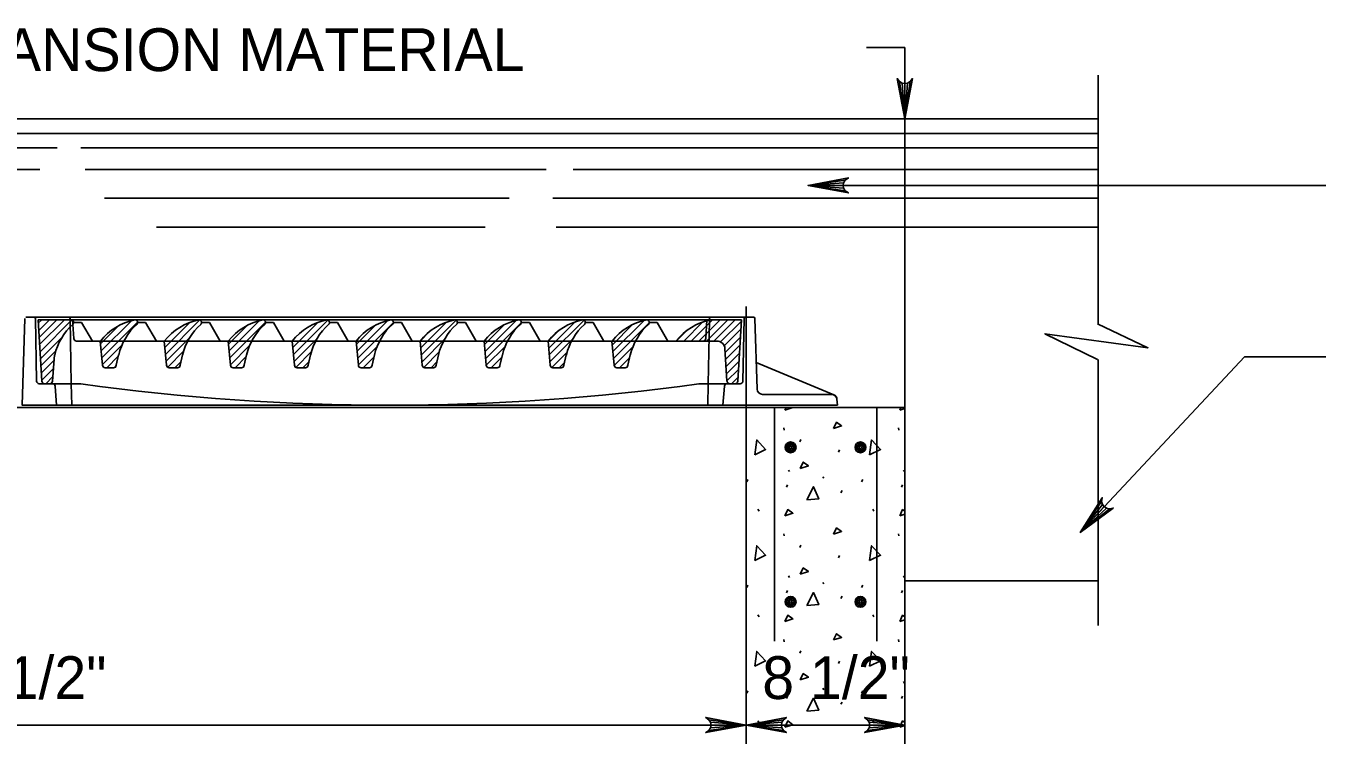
# Model space of a CAD drawing. Extents: x 6.91 to 13.84, y 0.35 to 9.99.
# Drawn here: x 8.632 to 10.454, y 6.724 to 7.719 of the extents above; entities that cross this region are included whole.
import ezdxf

# ---------------------------------------------------------------- set-up
doc = ezdxf.new("R2010")
doc.units = 0
for name, color, linetype in [('DETL-DIMS', 7, 'Continuous'), ('DETL-LINE', 7, 'Continuous'), ('DETL-NOTE', 7, 'Continuous'), ('DETL-PATT', 7, 'Continuous')]:
    doc.layers.add(name, color=color, linetype=linetype)

msp = doc.modelspace()

# ---------------------------------------------------------------- linework, layer by layer
at = {"layer": 'DETL-DIMS'}
for p, q in [((9.81, 7.6883), (9.864, 7.6883)), ((9.864, 7.5885), (9.864, 7.6883)), ((10.4542, 7.4952), (9.7283, 7.4952)), ((10.3402, 7.255), (10.1097, 7.0091)), ((10.3402, 7.255), (10.4542, 7.255)), ((7.619, 6.7391), (9.6416, 6.7391)), ((9.6416, 6.7391), (9.864, 6.7391))]:
    msp.add_line(p, q, dxfattribs=at)
for points in [[(9.864, 7.5885), (9.8534, 7.645), (9.8565, 7.6407), (9.8602, 7.6384), (9.864, 7.6378), (9.8678, 7.6384), (9.8716, 7.6407), (9.8746, 7.645), (9.864, 7.5885), (9.8716, 7.6407), (9.8678, 7.6384), (9.864, 7.5885), (9.864, 7.6378), (9.8602, 7.6384), (9.864, 7.5885), (9.8565, 7.6407)], [(9.7283, 7.4952), (9.7848, 7.5058), (9.7805, 7.5028), (9.7782, 7.499), (9.7776, 7.4952), (9.7782, 7.4914), (9.7805, 7.4876), (9.7848, 7.4846), (9.7283, 7.4952), (9.7805, 7.4876), (9.7782, 7.4914), (9.7283, 7.4952), (9.7776, 7.4952), (9.7782, 7.499), (9.7283, 7.4952), (9.7805, 7.5028)], [(10.1097, 7.0091), (10.1406, 7.0576), (10.1398, 7.0524), (10.1411, 7.0482), (10.1434, 7.0451), (10.1466, 7.043), (10.1509, 7.042), (10.1561, 7.0431), (10.1097, 7.0091), (10.1509, 7.042), (10.1466, 7.043), (10.1097, 7.0091), (10.1434, 7.0451), (10.1411, 7.0482), (10.1097, 7.0091), (10.1398, 7.0524)], [(9.6416, 6.7391), (9.585, 6.7285), (9.5894, 6.7315), (9.5916, 6.7353), (9.5923, 6.7391), (9.5916, 6.7429), (9.5894, 6.7466), (9.585, 6.7497), (9.6416, 6.7391), (9.5894, 6.7466), (9.5916, 6.7429), (9.6416, 6.7391), (9.5923, 6.7391), (9.5916, 6.7353), (9.6416, 6.7391), (9.5894, 6.7315)], [(9.6416, 6.7391), (9.6981, 6.7285), (9.6938, 6.7315), (9.6915, 6.7353), (9.6909, 6.7391), (9.6915, 6.7429), (9.6938, 6.7466), (9.6981, 6.7497), (9.6416, 6.7391), (9.6938, 6.7466), (9.6915, 6.7429), (9.6416, 6.7391), (9.6909, 6.7391), (9.6915, 6.7353), (9.6416, 6.7391), (9.6938, 6.7315)], [(9.864, 6.7391), (9.8075, 6.7285), (9.8118, 6.7315), (9.8141, 6.7353), (9.8147, 6.7391), (9.8141, 6.7429), (9.8118, 6.7466), (9.8075, 6.7497), (9.864, 6.7391), (9.8118, 6.7466), (9.8141, 6.7429), (9.864, 6.7391), (9.8147, 6.7391), (9.8141, 6.7353), (9.864, 6.7391), (9.8118, 6.7315)]]:
    msp.add_lwpolyline(points, dxfattribs=at)
at = {"layer": 'DETL-LINE'}
for p, q in [((10.1347, 7.6498), (10.1347, 7.3013)), ((9.864, 7.5885), (7.3965, 7.5885)), ((9.864, 7.5885), (10.1347, 7.5885)), ((9.864, 7.5885), (9.864, 7.1839)), ((9.6416, 7.3255), (9.6416, 5.8086)), ((9.6519, 7.3107), (8.6322, 7.3107)), ((8.6435, 7.3107), (8.6322, 7.3107)), ((8.6471, 7.221), (8.6454, 7.3089)), ((8.6471, 7.221), (8.6454, 7.3089)), ((8.6494, 7.302), (8.6544, 7.307)), ((8.65, 7.292), (8.665, 7.307)), ((8.6506, 7.2821), (8.6755, 7.307)), ((8.6512, 7.2721), (8.6861, 7.307)), ((8.6519, 7.2622), (8.6964, 7.3067)), ((8.694, 7.307), (8.6939, 7.3089)), ((8.6957, 7.2173), (8.694, 7.307)), ((8.6976, 7.307), (8.6992, 7.2806)), ((8.8278, 7.2585), (8.876, 7.3067)), ((9.0071, 7.2582), (9.0554, 7.3066)), ((9.1864, 7.2579), (9.2349, 7.3064)), ((9.3657, 7.2576), (9.4143, 7.3063)), ((9.5647, 7.2771), (9.5946, 7.307)), ((9.5753, 7.2771), (9.6052, 7.307)), ((9.5866, 7.307), (9.5849, 7.2806)), ((9.5858, 7.2771), (9.6157, 7.307)), ((9.5884, 7.2173), (9.5902, 7.3067)), ((9.5902, 7.307), (9.5902, 7.3089)), ((9.5964, 7.2771), (9.6263, 7.307)), ((9.637, 7.221), (9.6388, 7.3089)), ((9.6388, 7.3089), (9.637, 7.221)), ((9.6519, 7.3107), (9.6407, 7.3107)), ((9.6538, 7.3089), (9.6568, 7.2096)), ((9.6568, 7.2096), (9.6538, 7.3089)), ((8.7368, 7.2731), (8.7623, 7.2987)), ((8.7377, 7.2635), (8.7799, 7.3057)), ((8.7386, 7.2538), (8.7885, 7.3038)), ((8.8269, 7.2682), (8.862, 7.3033)), ((8.9161, 7.2729), (8.9423, 7.2991)), ((8.917, 7.2632), (8.9596, 7.3058)), ((8.9179, 7.2535), (8.9678, 7.3035)), ((9.0062, 7.2679), (9.0418, 7.3035)), ((9.0954, 7.2726), (9.1222, 7.2994)), ((9.0963, 7.2629), (9.1393, 7.3059)), ((9.0972, 7.2532), (9.1472, 7.3032)), ((9.1854, 7.2781), (9.1968, 7.2895)), ((9.1855, 7.2676), (9.2215, 7.3036)), ((9.2747, 7.2723), (9.3022, 7.2998)), ((9.2756, 7.2626), (9.319, 7.306)), ((9.2765, 7.2529), (9.3264, 7.3029)), ((9.3639, 7.277), (9.3775, 7.2906)), ((9.3648, 7.2673), (9.4013, 7.3038)), ((9.454, 7.272), (9.4821, 7.3002)), ((9.4549, 7.2623), (9.4987, 7.3061)), ((9.4558, 7.2527), (9.5056, 7.3025)), ((9.5436, 7.2771), (9.5583, 7.2918)), ((9.5541, 7.2771), (9.581, 7.304)), ((9.6058, 7.2759), (9.635, 7.3051)), ((9.6109, 7.2705), (9.6343, 7.2938)), ((8.6525, 7.2522), (8.6829, 7.2826)), ((8.703, 7.2771), (9.532, 7.2771)), ((8.7394, 7.2441), (8.7666, 7.2712)), ((8.8286, 7.2488), (8.8617, 7.2819)), ((8.9187, 7.2438), (8.9456, 7.2707)), ((9.008, 7.2485), (9.0406, 7.2811)), ((9.0087, 7.281), (9.0155, 7.2878)), ((9.098, 7.2435), (9.1247, 7.2702)), ((9.1873, 7.2482), (9.2194, 7.2804)), ((9.3666, 7.248), (9.3983, 7.2797)), ((9.6122, 7.2612), (9.6336, 7.2826)), ((9.6128, 7.2513), (9.6328, 7.2713)), ((8.6531, 7.2423), (8.674, 7.2632)), ((8.7456, 7.2397), (8.7616, 7.2558)), ((8.8308, 7.2404), (8.8532, 7.2628)), ((8.9252, 7.2397), (8.9408, 7.2553)), ((9.0103, 7.2403), (9.0323, 7.2623)), ((9.1048, 7.2397), (9.12, 7.2549)), ((9.1898, 7.2402), (9.2115, 7.2619)), ((9.2773, 7.2433), (9.3038, 7.2697)), ((9.2844, 7.2397), (9.2992, 7.2545)), ((9.3693, 7.2401), (9.3906, 7.2615)), ((9.4567, 7.243), (9.4829, 7.2692)), ((9.464, 7.2397), (9.4784, 7.2541)), ((9.6135, 7.2413), (9.6321, 7.26)), ((8.6537, 7.2323), (8.6718, 7.2505)), ((8.6543, 7.2224), (8.6709, 7.2389)), ((8.7566, 7.2402), (8.7582, 7.2418)), ((8.8407, 7.2397), (8.8496, 7.2486)), ((8.9369, 7.2409), (8.937, 7.2409)), ((9.0203, 7.2397), (9.0288, 7.2482)), ((9.1999, 7.2397), (9.208, 7.2478)), ((9.3795, 7.2397), (9.3872, 7.2474)), ((9.6141, 7.2314), (9.6314, 7.2487)), ((9.6147, 7.2215), (9.6307, 7.2375)), ((9.6557, 7.2472), (9.7645, 7.2017)), ((10.1347, 7.2512), (10.1347, 6.8784)), ((8.6692, 7.2173), (8.6509, 7.2173)), ((8.6598, 7.2173), (8.6699, 7.2274)), ((8.6963, 7.1875), (8.6957, 7.2173)), ((9.5879, 7.1875), (9.5884, 7.2173)), ((9.615, 7.2173), (9.6333, 7.2173)), ((9.6184, 7.2173), (9.615, 7.2173)), ((9.6333, 7.2173), (9.6185, 7.2173)), ((9.6212, 7.2173), (9.63, 7.2262)), ((8.6752, 7.1875), (8.6729, 7.2139)), ((9.609, 7.1875), (9.6113, 7.2139)), ((9.6643, 7.2024), (9.7614, 7.2024)), ((9.7614, 7.2024), (9.6643, 7.2024)), ((9.7645, 7.2017), (9.764, 7.2019)), ((9.864, 7.1839), (7.3965, 7.1839)), ((9.7695, 7.1875), (8.6267, 7.1875)), ((9.6811, 7.1839), (9.6811, 6.8566)), ((9.6959, 7.1803), (9.6975, 7.1839)), ((9.7071, 7.1839), (9.6959, 7.1803)), ((9.7695, 7.1875), (9.7688, 7.1956)), ((9.8245, 7.1839), (9.8245, 6.8566)), ((9.8569, 7.1803), (9.8585, 7.1839)), ((9.864, 7.1826), (9.8569, 7.1803)), ((9.864, 5.6468), (9.864, 7.1839)), ((9.6943, 7.1554), (9.6947, 7.1522)), ((9.8553, 7.1554), (9.8557, 7.1522)), ((9.7168, 7.1361), (9.718, 7.1393)), ((9.7711, 7.1216), (9.7724, 7.1248)), ((9.7011, 7.0962), (9.7023, 7.0942)), ((9.8621, 7.0962), (9.8633, 7.0942)), ((9.6423, 7.0801), (9.6439, 7.0833)), ((9.6983, 7.0725), (9.6995, 7.0757)), ((9.749, 7.087), (9.7506, 7.0849)), ((9.8034, 7.0801), (9.805, 7.0833)), ((9.8593, 7.0725), (9.8605, 7.0757)), ((9.7744, 7.0644), (9.776, 7.0676)), ((9.658, 7.0415), (9.6596, 7.039)), ((9.8191, 7.0415), (9.8207, 7.039)), ((9.864, 7.0345), (9.8569, 7.0322)), ((9.6943, 7.0072), (9.6947, 7.004)), ((9.8553, 7.0072), (9.8557, 7.004)), ((9.7168, 6.9879), (9.718, 6.9911)), ((9.7711, 6.9734), (9.7724, 6.9766)), ((9.7011, 6.9481), (9.7023, 6.946)), ((9.8621, 6.9481), (9.8633, 6.946)), ((9.6423, 6.932), (9.6439, 6.9352)), ((9.6983, 6.9243), (9.6995, 6.9275)), ((9.749, 6.9388), (9.7506, 6.9368)), ((9.8034, 6.932), (9.805, 6.9352)), ((9.8593, 6.9243), (9.8605, 6.9275)), ((9.864, 6.9412), (10.1347, 6.9412)), ((9.7744, 6.9163), (9.776, 6.9195)), ((9.658, 6.8933), (9.6596, 6.8909)), ((9.8191, 6.8933), (9.8207, 6.8909)), ((9.864, 6.8863), (9.8569, 6.8841)), ((9.6943, 6.8591), (9.6947, 6.8559)), ((9.8553, 6.8591), (9.8557, 6.8559)), ((9.7168, 6.8398), (9.718, 6.843)), ((9.7711, 6.8253), (9.7724, 6.8285)), ((9.7011, 6.7999), (9.7023, 6.7979)), ((9.8621, 6.7999), (9.8633, 6.7979)), ((9.6423, 6.7838), (9.6439, 6.787)), ((9.6983, 6.7762), (9.6995, 6.7794)), ((9.749, 6.7907), (9.7506, 6.7886)), ((9.8034, 6.7838), (9.805, 6.787)), ((9.8593, 6.7762), (9.8605, 6.7794)), ((9.7744, 6.7681), (9.776, 6.7713)), ((9.658, 6.7452), (9.6596, 6.7427)), ((9.8191, 6.7452), (9.8207, 6.7427)), ((9.864, 6.7382), (9.8569, 6.7359))]:
    msp.add_line(p, q, dxfattribs=at)
for points in [[(8.6304, 7.3089), (8.6267, 7.1875), (8.6752, 7.1875), (8.6729, 7.2139)], [(10.1341, 7.2512), (10.0604, 7.2873), (10.2047, 7.2677), (10.1341, 7.3013)], [(8.6692, 7.2173), (8.6656, 7.2173), (8.6582, 7.2173), (8.6509, 7.2173)], [(9.6113, 7.2139), (9.609, 7.1875), (9.7695, 7.1875), (9.7688, 7.1956)], [(9.7639, 7.1546), (9.7683, 7.1634), (9.7752, 7.1582), (9.7639, 7.1546)], [(9.6536, 7.1179), (9.6564, 7.1385), (9.6689, 7.1252), (9.6536, 7.1179)], [(9.8146, 7.1179), (9.8174, 7.1385), (9.8299, 7.1252), (9.8146, 7.1179)], [(9.7172, 7.0986), (9.7216, 7.1075), (9.7289, 7.1022), (9.7172, 7.0986)], [(9.7265, 7.0547), (9.7361, 7.0729), (9.7434, 7.056), (9.7265, 7.0547)], [(9.6959, 7.0322), (9.6999, 7.0411), (9.7071, 7.0358), (9.6959, 7.0322)], [(9.8569, 7.0322), (9.8609, 7.0411), (9.864, 7.0388)], [(9.7639, 7.0064), (9.7683, 7.0153), (9.7752, 7.0101), (9.7639, 7.0064)], [(9.6536, 6.9698), (9.6564, 6.9903), (9.6689, 6.977), (9.6536, 6.9698)], [(9.8146, 6.9698), (9.8174, 6.9903), (9.8299, 6.977), (9.8146, 6.9698)], [(9.7172, 6.9505), (9.7216, 6.9593), (9.7289, 6.9541), (9.7172, 6.9505)], [(9.7265, 6.9066), (9.7361, 6.9247), (9.7434, 6.9078), (9.7265, 6.9066)], [(9.6959, 6.8841), (9.6999, 6.8929), (9.7071, 6.8877), (9.6959, 6.8841)], [(9.8569, 6.8841), (9.8609, 6.8929), (9.864, 6.8907)], [(9.7639, 6.8583), (9.7683, 6.8671), (9.7752, 6.8619), (9.7639, 6.8583)], [(9.6536, 6.8217), (9.6564, 6.8422), (9.6689, 6.8289), (9.6536, 6.8217)], [(9.8146, 6.8217), (9.8174, 6.8422), (9.8299, 6.8289), (9.8146, 6.8217)], [(9.7172, 6.8023), (9.7216, 6.8112), (9.7289, 6.806), (9.7172, 6.8023)], [(9.7265, 6.7585), (9.7361, 6.7766), (9.7434, 6.7597), (9.7265, 6.7585)], [(9.6959, 6.7359), (9.6999, 6.7448), (9.7071, 6.7395), (9.6959, 6.7359)], [(9.8569, 6.7359), (9.8609, 6.7448), (9.864, 6.7425)]]:
    msp.add_lwpolyline(points, dxfattribs=at)
for centre, radius in [((9.7039, 7.1282), 0.00758), ((9.7039, 7.1282), 0.00569), ((9.7039, 7.1282), 0.00379), ((9.7039, 7.1282), 0.0019), ((9.8017, 7.1282), 0.00758), ((9.8017, 7.1282), 0.00569), ((9.8017, 7.1282), 0.00379), ((9.8017, 7.1282), 0.0019), ((9.7039, 6.9117), 0.00758), ((9.7039, 6.9117), 0.00569), ((9.7039, 6.9117), 0.00379), ((9.7039, 6.9117), 0.0019), ((9.8017, 6.9117), 0.00758), ((9.8017, 6.9117), 0.00569), ((9.8017, 6.9117), 0.00379), ((9.8017, 6.9117), 0.0019)]:
    msp.add_circle(centre, radius, dxfattribs=at)
for centre, radius, start, end in [((8.6435, 7.3088), 0.00187, 1.1458, 90), ((8.6435, 7.3088), 0.00187, 1.1458, 90), ((8.6921, 7.3088), 0.00187, 1.1222, 90), ((9.5921, 7.3088), 0.00187, 90, 178.8778), ((9.6407, 7.3088), 0.00187, 90, 178.8542), ((9.6407, 7.3088), 0.00187, 90, 178.8542), ((9.6519, 7.3088), 0.00187, 1.7855, 90), ((9.6519, 7.3088), 0.00187, 1.7855, 90), ((8.703, 7.2808), 0.00373, 183.5874, 270.0007), ((9.5812, 7.2808), 0.00373, 269.9993, 356.4126), ((8.6509, 7.2211), 0.00373, 181.1458, 270), ((8.6509, 7.2211), 0.00373, 181.1458, 270), ((8.6692, 7.2136), 0.00373, 5, 90), ((8.6692, 7.2136), 0.00373, 5, 90), ((9.615, 7.2136), 0.00373, 90, 175), ((9.615, 7.2136), 0.00373, 90, 175), ((9.6185, 7.2211), 0.00373, 268.8729, 271.1271), ((9.6333, 7.2211), 0.00373, 270, 358.8542), ((9.6333, 7.2211), 0.00373, 270, 358.8542), ((9.6643, 7.2099), 0.00747, 181.7416, 270), ((9.6643, 7.2099), 0.00747, 181.7416, 270), ((9.7614, 7.1949), 0.00747, 5, 90), ((9.7614, 7.1949), 0.00747, 69.5728, 90), ((9.7614, 7.1949), 0.00747, 5, 65.0296)]:
    msp.add_arc(centre, radius, start, end, dxfattribs=at)
at = {"layer": 'DETL-NOTE'}
for p, q in [((8.6454, 7.3107), (8.6454, 7.3107)), ((9.6351, 7.307), (8.6491, 7.307)), ((8.6491, 7.307), (8.6544, 7.2208)), ((9.6351, 7.307), (9.6297, 7.2208)), ((9.6351, 7.307), (9.6351, 7.307)), ((9.6388, 7.3107), (9.6388, 7.3107)), ((9.6501, 7.3107), (9.6501, 7.3107)), ((9.6537, 7.3107), (9.6537, 7.3107)), ((8.699, 7.3032), (8.7102, 7.3032)), ((8.7252, 7.2771), (8.7102, 7.3032)), ((8.7886, 7.3032), (8.7998, 7.3032)), ((8.8149, 7.2771), (8.7998, 7.3032)), ((8.8783, 7.3032), (8.8895, 7.3032)), ((8.9045, 7.2771), (8.8895, 7.3032)), ((8.9679, 7.3032), (8.9791, 7.3032)), ((8.9941, 7.2771), (8.9791, 7.3032)), ((9.0576, 7.3032), (9.0688, 7.3032)), ((9.0838, 7.2771), (9.0688, 7.3032)), ((9.1472, 7.3032), (9.1584, 7.3032)), ((9.1734, 7.2771), (9.1584, 7.3032)), ((9.2368, 7.3032), (9.248, 7.3032)), ((9.263, 7.2771), (9.248, 7.3032)), ((9.3265, 7.3032), (9.3377, 7.3032)), ((9.3527, 7.2771), (9.3377, 7.3032)), ((9.4161, 7.3032), (9.4273, 7.3032)), ((9.4423, 7.2771), (9.4273, 7.3032)), ((9.5057, 7.3032), (9.5169, 7.3032)), ((9.532, 7.2771), (9.5169, 7.3032)), ((8.7364, 7.2771), (8.7252, 7.2771)), ((8.7364, 7.2771), (8.7395, 7.2432)), ((8.8261, 7.2771), (8.8149, 7.2771)), ((8.8261, 7.2771), (8.8292, 7.2432)), ((8.9157, 7.2771), (8.9045, 7.2771)), ((8.9157, 7.2771), (8.9188, 7.2432)), ((9.0053, 7.2771), (8.9941, 7.2771)), ((9.0053, 7.2771), (9.0084, 7.2432)), ((9.095, 7.2771), (9.0838, 7.2771)), ((9.095, 7.2771), (9.0981, 7.2432)), ((9.1846, 7.2771), (9.1734, 7.2771)), ((9.1846, 7.2771), (9.1877, 7.2432)), ((9.2742, 7.2771), (9.263, 7.2771)), ((9.2742, 7.2771), (9.2773, 7.2432)), ((9.3639, 7.2771), (9.3527, 7.2771)), ((9.3639, 7.2771), (9.367, 7.2432)), ((9.4535, 7.2771), (9.4423, 7.2771)), ((9.4535, 7.2771), (9.4566, 7.2432)), ((9.5432, 7.2771), (9.532, 7.2771)), ((9.6007, 7.2771), (9.5432, 7.2771)), ((9.6007, 7.2771), (9.6007, 7.2771)), ((8.6724, 7.2576), (8.6694, 7.2208)), ((8.7587, 7.2432), (8.7621, 7.2576)), ((8.8483, 7.2432), (8.8517, 7.2576)), ((8.938, 7.2432), (8.9413, 7.2576)), ((9.0276, 7.2432), (9.031, 7.2576)), ((9.1173, 7.2432), (9.1206, 7.2576)), ((9.2069, 7.2432), (9.2103, 7.2576)), ((9.2965, 7.2432), (9.2999, 7.2576)), ((9.3862, 7.2432), (9.3895, 7.2576)), ((9.4758, 7.2432), (9.4792, 7.2576)), ((9.6119, 7.2666), (9.6147, 7.2208)), ((8.755, 7.2397), (8.7433, 7.2397)), ((8.8446, 7.2397), (8.8329, 7.2397)), ((8.9343, 7.2397), (8.9225, 7.2397)), ((9.0239, 7.2397), (9.0122, 7.2397)), ((9.1135, 7.2397), (9.1018, 7.2397)), ((9.2032, 7.2397), (9.1914, 7.2397)), ((9.2928, 7.2397), (9.2811, 7.2397)), ((9.3824, 7.2397), (9.3707, 7.2397)), ((9.4721, 7.2397), (9.4603, 7.2397)), ((9.4721, 7.2397), (9.4721, 7.2397)), ((8.6656, 7.2173), (8.6582, 7.2173)), ((8.7088, 7.2173), (8.6656, 7.2173)), ((9.6184, 7.2173), (9.5753, 7.2173)), ((9.626, 7.2173), (9.6184, 7.2173)), ((9.626, 7.2173), (9.626, 7.2173)), ((9.6333, 7.2173), (9.6333, 7.2173)), ((8.6752, 7.1875), (8.6752, 7.1875)), ((9.609, 7.1875), (9.609, 7.1875)), ((9.7695, 7.1875), (9.7695, 7.1875))]:
    msp.add_line(p, q, dxfattribs=at)
for centre, radius, start, end in [((8.6953, 7.3032), 0.00373, 312.139, 90), ((8.8018, 7.2253), 0.0834, 101.6847, 141.6027), ((8.7849, 7.3032), 0.00373, 312.139, 90), ((8.8914, 7.2253), 0.0834, 101.6847, 141.6027), ((8.8745, 7.3032), 0.00373, 312.139, 90), ((8.9811, 7.2253), 0.0834, 101.6847, 141.6027), ((8.9642, 7.3032), 0.00373, 312.139, 90), ((9.0707, 7.2253), 0.0834, 101.6847, 141.6027), ((9.0538, 7.3032), 0.00373, 312.139, 90), ((9.1603, 7.2253), 0.0834, 101.6847, 141.6027), ((9.1435, 7.3032), 0.00373, 312.139, 90), ((9.25, 7.2253), 0.0834, 101.6847, 141.6027), ((9.2331, 7.3032), 0.00373, 312.139, 90), ((9.3396, 7.2253), 0.0834, 101.6847, 141.6027), ((9.3227, 7.3032), 0.00373, 312.139, 90), ((9.4293, 7.2253), 0.0834, 101.6847, 141.6027), ((9.4124, 7.3032), 0.00373, 312.139, 90), ((9.5189, 7.2253), 0.0834, 101.6847, 141.6027), ((9.502, 7.3032), 0.00373, 312.139, 90), ((9.6085, 7.2253), 0.0834, 101.6847, 141.6027), ((8.7537, 7.2385), 0.0834, 132.0547, 166.7971), ((8.8433, 7.2385), 0.0834, 132.0547, 166.7971), ((8.9329, 7.2385), 0.0834, 132.0547, 166.7971), ((9.0226, 7.2385), 0.0834, 132.0547, 166.7971), ((9.1122, 7.2385), 0.0834, 132.0547, 166.7971), ((9.2018, 7.2385), 0.0834, 132.0547, 166.7971), ((9.2915, 7.2385), 0.0834, 132.0547, 166.7971), ((9.3811, 7.2385), 0.0834, 132.0547, 166.7971), ((9.4708, 7.2385), 0.0834, 132.0547, 166.7971), ((9.5604, 7.2385), 0.0834, 132.0547, 166.7971), ((9.6007, 7.2659), 0.0112, 3.5763, 90), ((8.7433, 7.2435), 0.00373, 183.9735, 270), ((8.755, 7.2435), 0.00373, 270, 356.0265), ((8.8329, 7.2435), 0.00373, 183.9735, 270), ((8.8446, 7.2435), 0.00373, 270, 356.0265), ((8.9225, 7.2435), 0.00373, 183.9735, 270), ((8.9343, 7.2435), 0.00373, 270, 356.0265), ((9.0122, 7.2435), 0.00373, 183.9735, 270), ((9.0239, 7.2435), 0.00373, 270, 356.0265), ((9.1018, 7.2435), 0.00373, 183.9735, 270), ((9.1135, 7.2435), 0.00373, 270, 356.0265), ((9.1914, 7.2435), 0.00373, 183.9735, 270), ((9.2032, 7.2435), 0.00373, 270, 356.0265), ((9.2811, 7.2435), 0.00373, 183.9735, 270), ((9.2928, 7.2435), 0.00373, 270, 356.0265), ((9.3707, 7.2435), 0.00373, 183.9735, 270), ((9.3824, 7.2435), 0.00373, 270, 356.0265), ((9.4603, 7.2435), 0.00373, 183.9735, 270), ((9.4721, 7.2435), 0.00373, 270, 356.0265), ((8.6582, 7.2211), 0.00373, 183.5616, 270), ((8.6656, 7.2211), 0.00373, 270, 355.2441), ((9.1421, 10.3434), 3.156, 262.1096, 277.8904), ((9.6185, 7.2211), 0.00373, 183.5763, 270), ((9.626, 7.2211), 0.00373, 270, 356.4126)]:
    msp.add_arc(centre, radius, start, end, dxfattribs=at)
at = {"layer": 'DETL-PATT'}
for p, q in [((10.1347, 7.5682), (8.2049, 7.5682)), ((8.6759, 7.548), (8.2144, 7.548)), ((10.1347, 7.548), (8.7091, 7.548)), ((8.6517, 7.5177), (8.186, 7.5177)), ((9.3613, 7.5177), (8.7152, 7.5177)), ((10.1347, 7.5177), (9.3992, 7.5177)), ((9.3092, 7.4772), (8.7424, 7.4772)), ((10.1347, 7.4772), (9.3708, 7.4772)), ((9.276, 7.4368), (8.815, 7.4368)), ((10.1347, 7.4368), (9.3755, 7.4368))]:
    msp.add_line(p, q, dxfattribs=at)

# ---------------------------------------------------------------- texts
at = {"layer": 'DETL-NOTE'}
for s, p in [('CURVE JOINT WITH 1/4" EXPANSION MATERIAL', (7.4926, 7.6554)), ('5\'-6 1/2"', (8.4515, 6.7755)), ('8 1/2"', (9.6641, 6.7755))]:
    msp.add_text(s, height=0.06, dxfattribs=at).set_placement(p)

doc.saveas('drawing.dxf')
